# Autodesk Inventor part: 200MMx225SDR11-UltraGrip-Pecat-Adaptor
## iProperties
Created: 2012-06
Part Number: 200MMx225SDR11-UltraGrip-Pecat-Adaptor
Document SubType Name: Modeling
Designer: D Cole
Density: 1 g/cm^3
Author: D Cole
